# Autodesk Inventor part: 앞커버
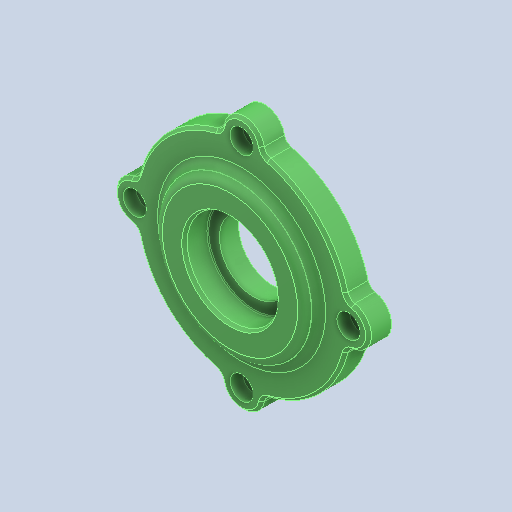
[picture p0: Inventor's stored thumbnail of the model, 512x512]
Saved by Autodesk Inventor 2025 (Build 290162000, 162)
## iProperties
Created: 2025-08
Part Number: 앞커버
Material: 알루미늄 6061
Document SubType Name: Modeling
Designer: infra04
Density: 2.71 g/cm^3
Appearance: 기본값
Company: 한국ATC센터
Author: jhkim
Sending System: Autodesk Inventor 2026
Preprocessor: ST-DEVELOPER v20.1
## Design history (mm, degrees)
feature "솔리드1"
node "솔리드2"
